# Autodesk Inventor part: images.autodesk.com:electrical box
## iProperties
Created: 2008-02
Material: Default
Document SubType Name: Sheet Metal
Designer: MSD
Density: 7.86 g/cm^3
Flat Pattern Width: 18.5216 cm
Flat Pattern Length: 25.7113 cm
Flat Pattern Area: 476.213 cm^2
Sheet Metal Rule: Steel 16 Ga
Length: =<FLAT PATTERN LENGTH> cm
Width: =<FLAT PATTERN WIDTH> cm
Author: Autodesk, Inc.
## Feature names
1. Corner Chamfer1
2. Hole1
3. Plate2
4. Plate3
5. Bend2
6. Plate4
7. Bend3
8. Plate5
9. Bend4
10. Cut1
